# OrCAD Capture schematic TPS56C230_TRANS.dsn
size E; title: TPS56C230: 4.5V to 18 V Input, 12-A Synchronous Step-Down; rev: 1.0; note: Datasheet: SLUSDE4     EVM: NA; note: Synchronous Step Down Converter; note: Voltage Regulator
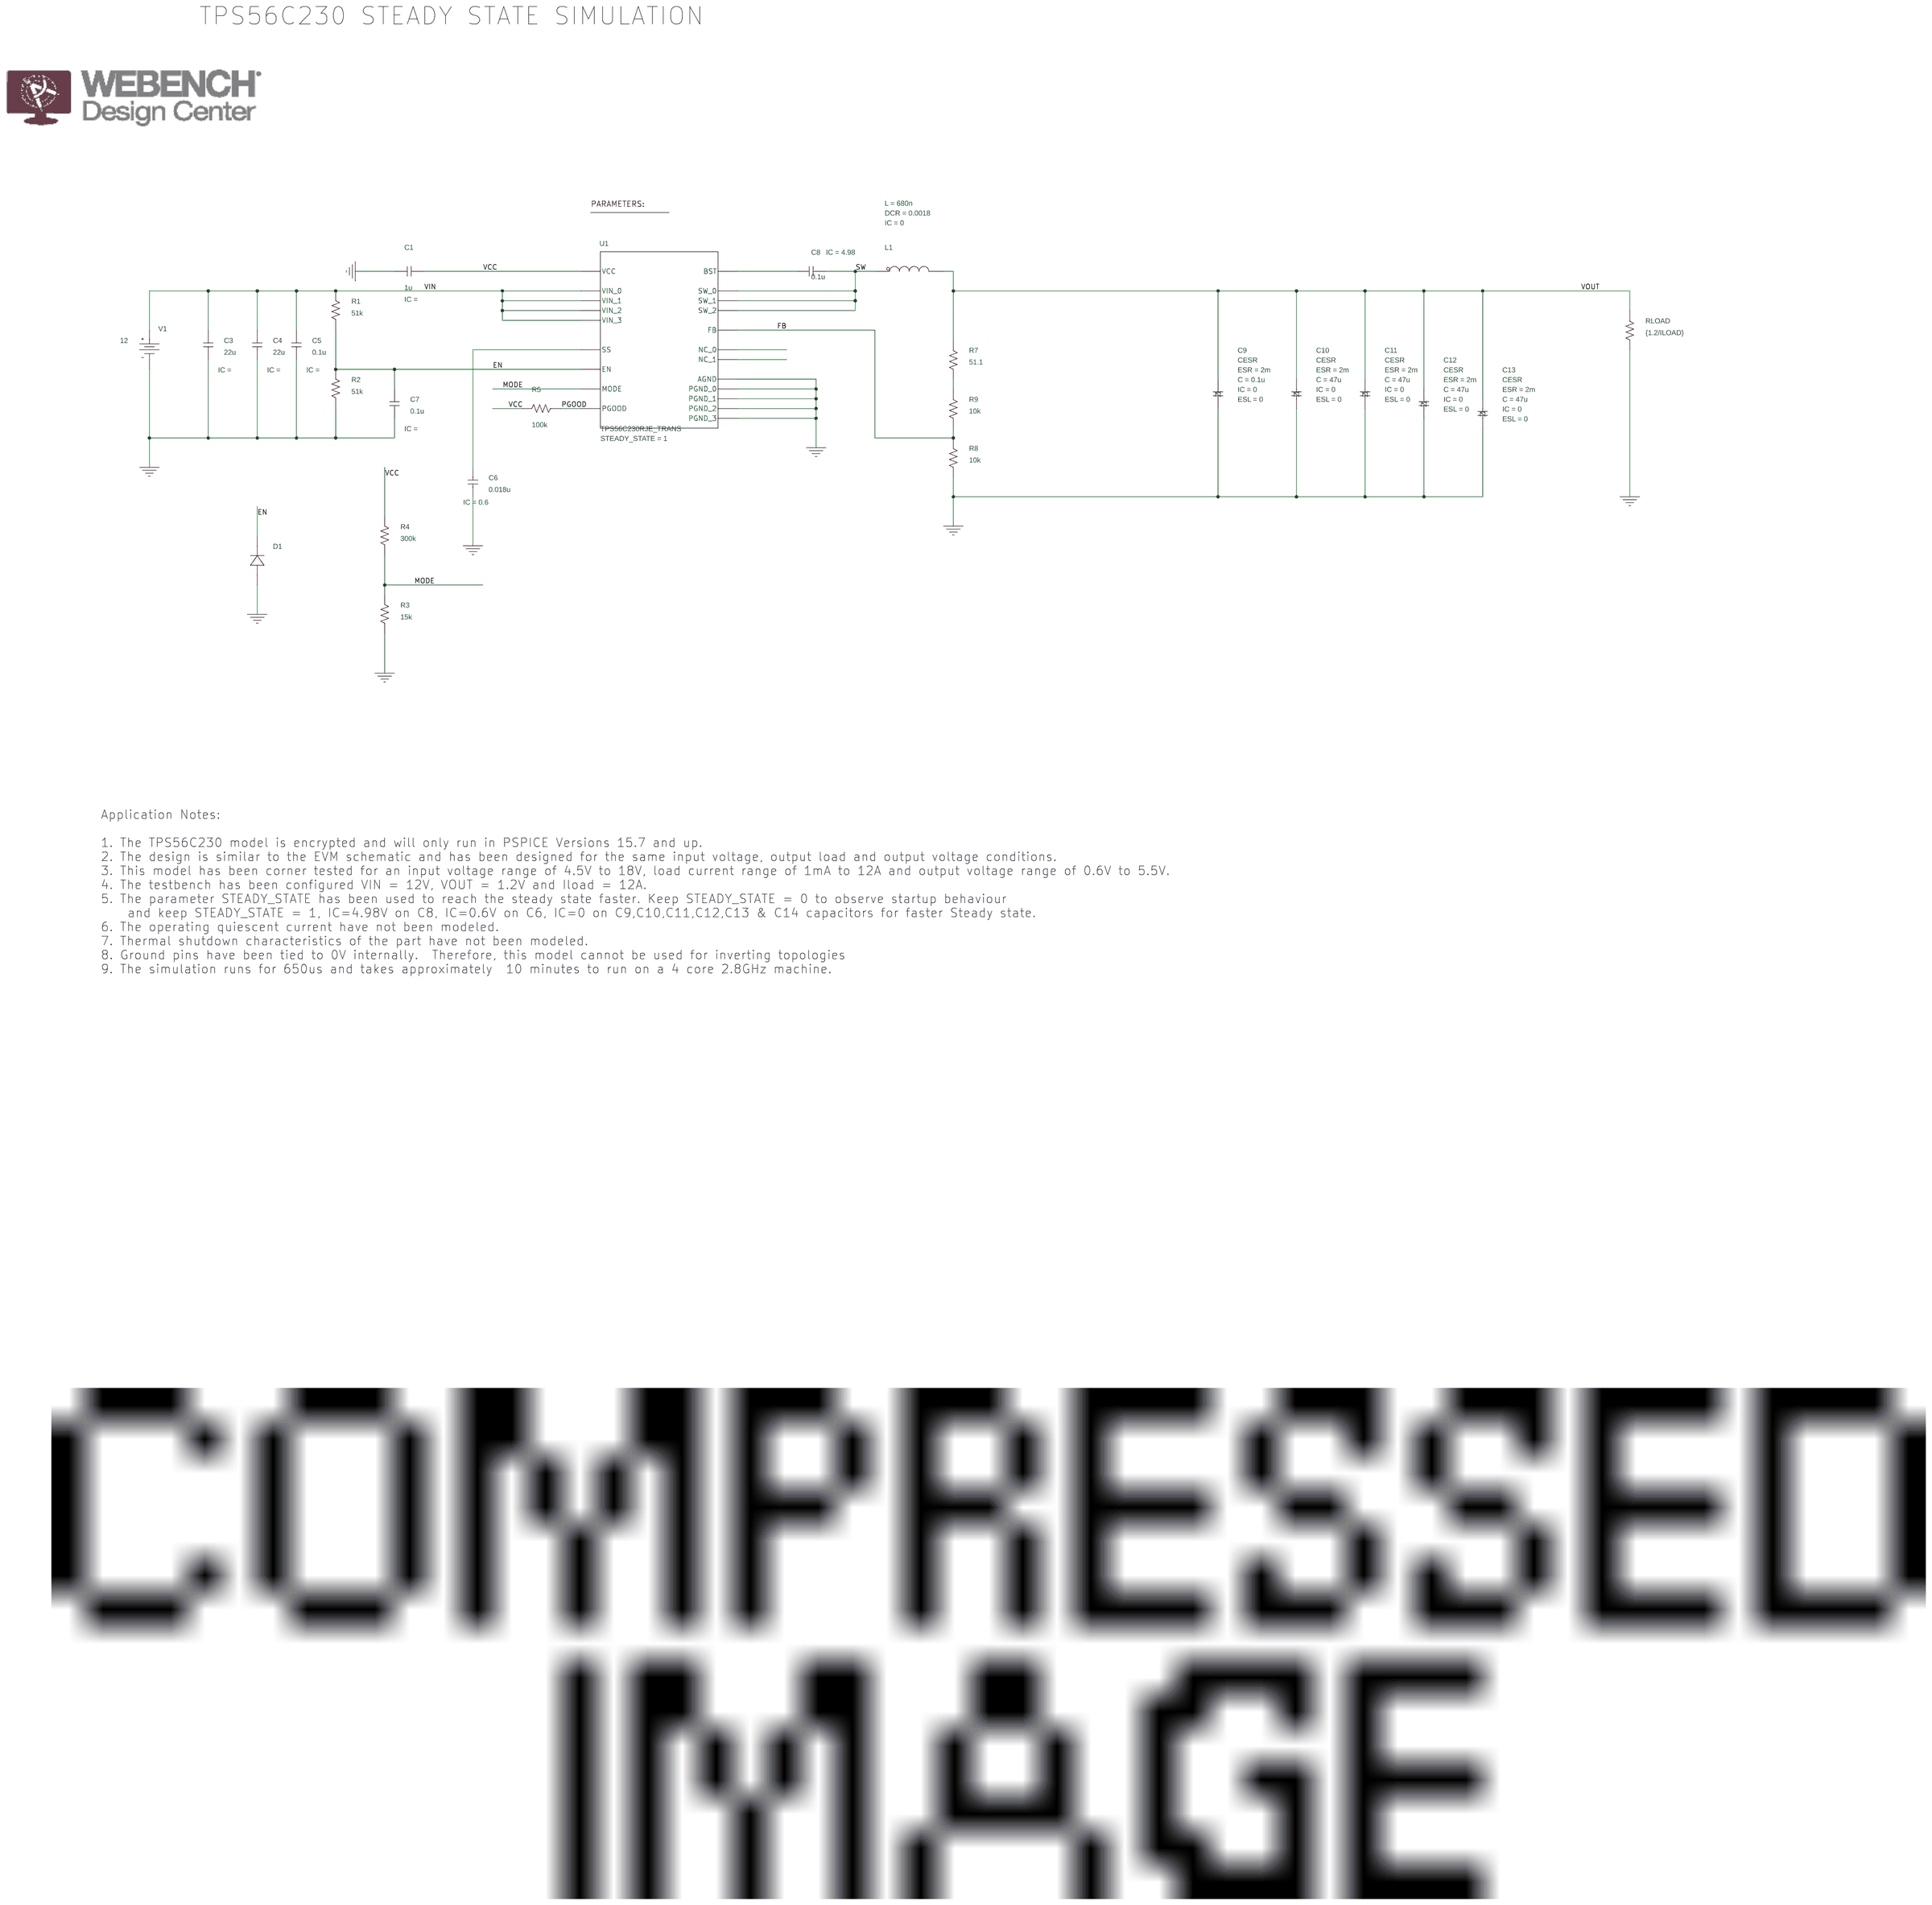
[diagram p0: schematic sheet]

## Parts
1  PARAM
C1  1u  [RAD/CK05]
C3  22u  [RAD/CK05]
C4  22u  [RAD/CK05]
C5  0.1u  [RAD/CK05]
C6  0.018u  [RAD/CK05]
C7  0.1u  [RAD/CK05]
C8  0.1u  [RAD/CK05]
C9  CESR
C10  CESR
C11  CESR
C12  CESR
C13  CESR
D1  D_D1
L1  LDCR
R1  51k  [AX/RC05]
R2  51k  [AX/RC05]
R3  15k  [AX/RC05]
R4  300k  [AX/RC05]
R5  100k  [AX/RC05]
R7  51.1  [AX/RC05]
R8  10k  [AX/RC05]
R9  10k  [AX/RC05]
RLOAD  {1.2/ILOAD}  [AX/RC05]
U1  TPS56C230RJE_TRANS
V1  VDC

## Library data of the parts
1 = PARAM: ILOAD: 12
C1 C3-C5 C7 = C
C6 = C: IC: 0.6
C8 = C: IC: 4.98
C9 = CESR_1: C: 0.1u; ESL: 0; ESR: 2m; IC: 0; PSpiceTemplate: X^@REFDES %1 %2 @MODEL PARAMS: ?C|C=@C||C=10U| ?ESR|ESR=@ESR||ESR=2M| ?IC|IC=@IC||IC=1N|; X: 1
C10 = CESR_2: C: 47u; ESL: 0; ESR: 2m; IC: 0; PSpiceTemplate: X^@REFDES %1 %2 @MODEL PARAMS: ?C|C=@C||C=10U| ?ESR|ESR=@ESR||ESR=2M| ?IC|IC=@IC||IC=1N|; X: 1
C11 = CESR_3: C: 47u; ESL: 0; ESR: 2m; IC: 0; PSpiceTemplate: X^@REFDES %1 %2 @MODEL PARAMS: ?C|C=@C||C=10U| ?ESR|ESR=@ESR||ESR=2M| ?IC|IC=@IC||IC=1N|; X: 1
C12 = CESR: C: 47u; ESL: 0; ESR: 2m; IC: 0; PSpiceTemplate: X^@REFDES %1 %2 @MODEL PARAMS: ?C|C=@C||C=10U| ?ESR|ESR=@ESR||ESR=2M| ?IC|IC=@IC||IC=1N|; X: 1
C13 = CESR_4: C: 47u; ESL: 0; ESR: 2m; IC: 0; PSpiceTemplate: X^@REFDES %1 %2 @MODEL PARAMS: ?C|C=@C||C=10U| ?ESR|ESR=@ESR||ESR=2M| ?IC|IC=@IC||IC=1N|; X: 1
D1 = D_D1: PSpiceTemplate: x^@REFDES %A %C @MODEL ?AREA/@AREA/
L1 = LDCR_0: DCR: 0.0018; IC: 0; L: 680n; PSpiceTemplate: X^@REFDES %IN %OUT @MODEL PARAMS:  ?L|L=@L||L=1u|  ?DCR|DCR=@DCR||DCR=0.01| ?IC|IC=@IC||IC=0|
R1-R5 R7-R9 RLOAD = R
U1 = TPS56C230RJE_TRANS: STEADY_STATE: 1
V1 = VDC: DC: 12

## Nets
VCC: C1.1 R4.2 R5.2 U1.VCC
VIN: C3.1 C4.1 C5.1 R1.2 U1.VIN_0 U1.VIN_1 U1.VIN_2 U1.VIN_3 V1.0(+)
0: C1.2 C3.2 C4.2 C5.2 C6.2 C7.2 C9.2 C10.2 C11.2 C12.2 C13.2 D1.2(A) R2.1 R3.1 R8.2 RLOAD.2 U1.AGND U1.PGND_0 U1.PGND_1 U1.PGND_2 U1.PGND_3 V1.1(-)
EN: C7.1 D1.1(C) R1.1 R2.2 U1.EN
FB: R8.1 R9.2 U1.FB
MODE: R3.2 R4.1 U1.MODE
PGOOD: R5.1 U1.PGOOD
SW: C8.2 L1.1(IN) U1.SW_0 U1.SW_1 U1.SW_2
VOUT: C9.1 C10.1 C11.1 C12.1 C13.1 L1.3(OUT) R7.1 RLOAD.1
N16770465: C8.1 U1.BST
N16770829: C6.1 U1.SS
N16770887: R7.2 R9.1

Not connected (* = marked no-connect by the designer): U1 NC_0 NC_1

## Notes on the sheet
- TPS56C230 STEADY STATE SIMULATION
- Application Notes:
  1. The TPS56C230 model is encrypted and will only run in PSPICE Versions 15.7 and up.
  2. The design is similar to the EVM schematic and has been designed for the same input voltage, output load and output voltage conditions.
  3. This model has been corner tested for an input voltage range of 4.5V to 18V, load current range of 1mA to 12A and output voltage range of 0.6V to 5.5V.
  4. The testbench has been configured VIN = 12V, VOUT = 1.2V and Iload = 12A.
  5. The parameter STEADY_STATE has been used to reach the steady state faster. Keep STEADY_STATE = 0 to observe startup behaviour
      and keep STEADY_STATE = 1, IC=4.98V on C8, IC=0.6V on C6, IC=0 on C9,C10,C11,C12,C13 & C14 capacitors for faster Steady state.
  6. The operating quiescent current have not been modeled.
  7. Thermal shutdown characteristics of the part have not been modeled.
  8. Ground pins have been tied to 0V internally.  Therefore, this model cannot be used for inverting topologies
  9. The simulation runs for 650us and takes approximately  10 minutes to run on a 4 core 2.8GHz machine.
